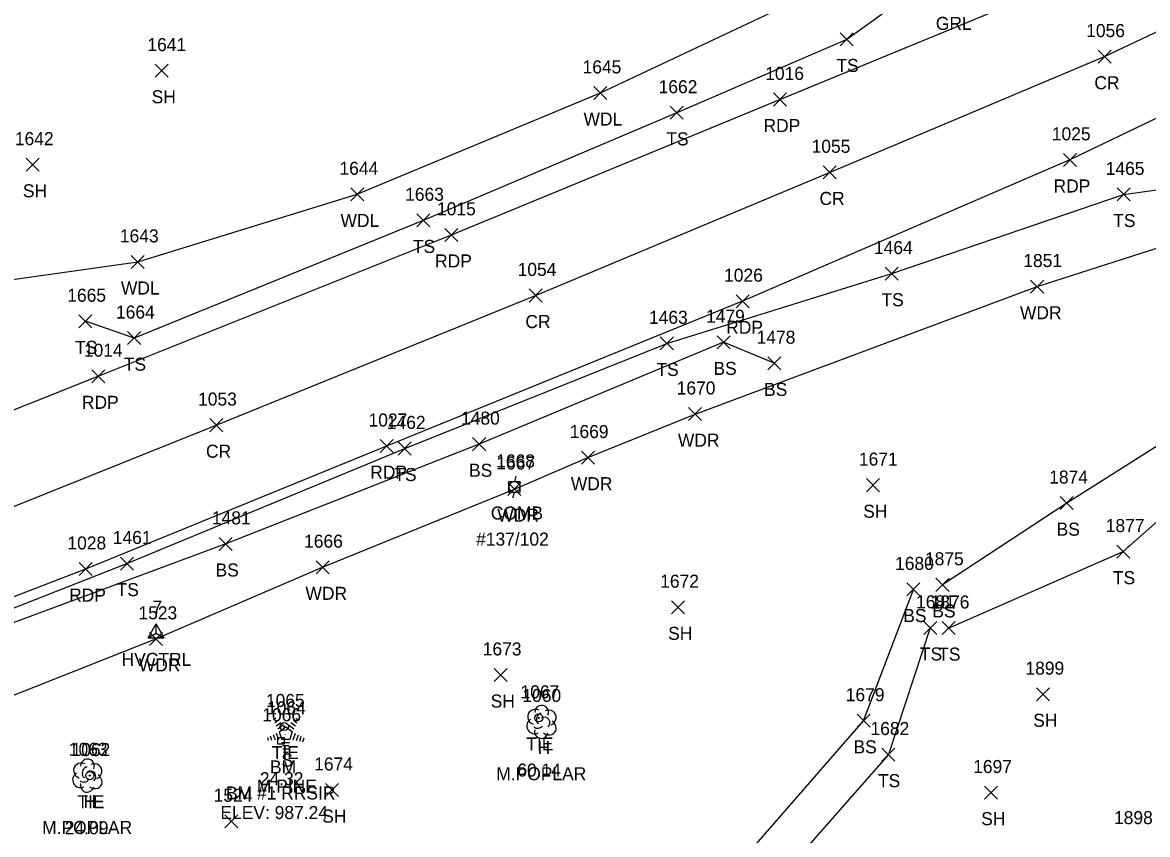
# Model space of a CAD drawing. Extents: x 1633660 to 1636532, y 388643 to 392631.
# Drawn here: x 1634224 to 1634396.6, y 388797.6 to 388922.1 of the extents above; entities that cross this region are included whole.
import ezdxf

# ---------------------------------------------------------------- set-up
doc = ezdxf.new("R2010")
doc.units = 0
for name, color, linetype in [('C_A', 7, 'Continuous'), ('C_C', 7, 'Continuous'), ('C_I', 7, 'Continuous'), ('CBP', 7, 'Continuous'), ('CPBM', 7, 'Continuous'), ('CPSM', 7, 'Continuous'), ('L_A', 7, 'Continuous'), ('L_C', 7, 'Continuous'), ('L_I', 7, 'Continuous'), ('L_TIC', 7, 'Continuous'), ('LAWA', 7, 'Continuous'), ('LELB', 7, 'Continuous'), ('LTC', 7, 'Continuous'), ('LTD', 7, 'Continuous'), ('P_A', 7, 'Continuous'), ('P_I', 7, 'Continuous'), ('P_TIC', 7, 'Continuous'), ('PET', 7, 'Continuous'), ('PRC', 7, 'Continuous'), ('R_A', 7, 'Continuous'), ('U_A', 7, 'Continuous'), ('U_C', 7, 'Continuous'), ('U_I', 7, 'Continuous'), ('UP', 7, 'Continuous')]:
    doc.layers.add(name, color=color, linetype=linetype)

msp = doc.modelspace()

# ---------------------------------------------------------------- linework, layer by layer
at = {"layer": 'CBP'}
for centre, radius in [((1634303.22, 388815.45), 0.625), ((1634264.16, 388814.12), 0.625), ((1634264.16, 388814.12), 0.0833), ((1634303.22, 388815.45), 0.0833), ((1634234.32, 388806.59), 0.625), ((1634234.32, 388806.59), 0.0833)]:
    msp.add_circle(centre, radius, dxfattribs=at)
at = {"layer": 'CPBM'}
for p, q in [((1634263.15, 388811.43), (1634263.15, 388812.43)), ((1634263.15, 388812.43), (1634264.15, 388812.43)), ((1634264.15, 388812.43), (1634264.15, 388811.43)), ((1634264.15, 388811.43), (1634263.15, 388811.43)), ((1634263.65, 388811.93), (1634263.65, 388811.93)), ((1634263.65, 388811.93), (1634263.65, 388811.93))]:
    msp.add_line(p, q, dxfattribs=at)
at = {"layer": 'CPSM'}
for p, q in [((1634243.25, 388827.71), (1634244.5, 388829.88)), ((1634245.75, 388827.71), (1634244.5, 388829.88)), ((1634244.5, 388828.43), (1634244.5, 388829.88)), ((1634243.25, 388827.71), (1634244.5, 388828.43)), ((1634243.25, 388827.71), (1634245.75, 388827.71)), ((1634244.5, 388828.43), (1634244.5, 388828.43)), ((1634244.5, 388828.43), (1634245.75, 388827.71))]:
    msp.add_line(p, q, dxfattribs=at)
at = {"layer": 'L_TIC'}
for points in [[(1634349.49, 388918.54), (1634351.49, 388920.54)], [(1634351.49, 388918.54), (1634349.49, 388920.54)], [(1634244.33, 388913.74), (1634246.33, 388915.74)], [(1634246.33, 388913.74), (1634244.33, 388915.74)], [(1634311.68, 388910.32), (1634313.68, 388912.32)], [(1634313.68, 388910.32), (1634311.68, 388912.32)], [(1634323.4, 388907.28), (1634325.4, 388909.28)], [(1634325.4, 388907.28), (1634323.4, 388909.28)], [(1634224.55, 388899.31), (1634226.55, 388901.31)], [(1634226.55, 388899.31), (1634224.55, 388901.31)], [(1634274.37, 388894.77), (1634276.37, 388896.77)], [(1634276.37, 388894.77), (1634274.37, 388896.77)], [(1634391.97, 388894.75), (1634393.97, 388896.75)], [(1634393.97, 388894.75), (1634391.97, 388896.75)], [(1634284.5, 388890.78), (1634286.5, 388892.78)], [(1634286.5, 388890.78), (1634284.5, 388892.78)], [(1634240.67, 388884.4), (1634242.67, 388886.4)], [(1634242.67, 388884.4), (1634240.67, 388886.4)], [(1634356.4, 388882.6), (1634358.4, 388884.6)], [(1634358.4, 388882.6), (1634356.4, 388884.6)], [(1634378.71, 388880.61), (1634380.71, 388882.61)], [(1634380.71, 388880.61), (1634378.71, 388882.61)], [(1634232.64, 388875.29), (1634234.64, 388877.29)], [(1634234.64, 388875.29), (1634232.64, 388877.29)], [(1634240.12, 388872.71), (1634242.12, 388874.71)], [(1634242.12, 388872.71), (1634240.12, 388874.71)], [(1634321.87, 388871.9), (1634323.87, 388873.9)], [(1634323.87, 388871.9), (1634321.87, 388873.9)], [(1634330.59, 388872.07), (1634332.59, 388874.07)], [(1634332.59, 388872.07), (1634330.59, 388874.07)], [(1634338.35, 388868.85), (1634340.35, 388870.85)], [(1634340.35, 388868.85), (1634338.35, 388870.85)], [(1634326.21, 388861.06), (1634328.21, 388863.06)], [(1634328.21, 388861.06), (1634326.21, 388863.06)], [(1634281.64, 388855.78), (1634283.64, 388857.78)], [(1634283.64, 388855.78), (1634281.64, 388857.78)], [(1634293.07, 388856.44), (1634295.07, 388858.44)], [(1634295.07, 388856.44), (1634293.07, 388858.44)], [(1634309.77, 388854.38), (1634311.77, 388856.38)], [(1634311.77, 388854.38), (1634309.77, 388856.38)], [(1634353.52, 388850.15), (1634355.52, 388852.15)], [(1634355.52, 388850.15), (1634353.52, 388852.15)], [(1634298.49, 388849.56), (1634300.49, 388851.56)], [(1634300.49, 388849.56), (1634298.49, 388851.56)], [(1634383.25, 388847.4), (1634385.25, 388849.4)], [(1634385.25, 388847.4), (1634383.25, 388849.4)], [(1634254.17, 388841.14), (1634256.17, 388843.14)], [(1634256.17, 388841.14), (1634254.17, 388843.14)], [(1634391.92, 388839.96), (1634393.92, 388841.96)], [(1634393.92, 388839.96), (1634391.92, 388841.96)], [(1634239.01, 388838.13), (1634241.01, 388840.13)], [(1634241.01, 388838.13), (1634239.01, 388840.13)], [(1634269.05, 388837.56), (1634271.05, 388839.56)], [(1634271.05, 388837.56), (1634269.05, 388839.56)], [(1634364.18, 388834.86), (1634366.18, 388836.86)], [(1634366.18, 388834.86), (1634364.18, 388836.86)], [(1634359.72, 388834.15), (1634361.72, 388836.15)], [(1634361.72, 388834.15), (1634359.72, 388836.15)], [(1634323.59, 388831.42), (1634325.59, 388833.42)], [(1634325.59, 388831.42), (1634323.59, 388833.42)], [(1634362.3, 388828.26), (1634364.3, 388830.26)], [(1634364.3, 388828.26), (1634362.3, 388830.26)], [(1634365.11, 388828.23), (1634367.11, 388830.23)], [(1634367.11, 388828.23), (1634365.11, 388830.23)], [(1634243.47, 388826.57), (1634245.47, 388828.57)], [(1634245.47, 388826.57), (1634243.47, 388828.57)], [(1634296.36, 388821.03), (1634298.36, 388823.03)], [(1634298.36, 388821.03), (1634296.36, 388823.03)], [(1634379.61, 388818.08), (1634381.61, 388820.08)], [(1634381.61, 388818.08), (1634379.61, 388820.08)], [(1634352.08, 388814.01), (1634354.08, 388816.01)], [(1634354.08, 388814.01), (1634352.08, 388816.01)], [(1634355.87, 388808.82), (1634357.87, 388810.82)], [(1634357.87, 388808.82), (1634355.87, 388810.82)], [(1634270.49, 388803.38), (1634272.49, 388805.38)], [(1634272.49, 388803.38), (1634270.49, 388805.38)], [(1634371.63, 388802.99), (1634373.63, 388804.99)], [(1634373.63, 388802.99), (1634371.63, 388804.99)], [(1634255.02, 388798.58), (1634257.02, 388800.58)], [(1634257.02, 388798.58), (1634255.02, 388800.58)]]:
    msp.add_lwpolyline(points, dxfattribs=at)
at = {"layer": 'LAWA'}
for points in [[(1634029.51, 388906.75), (1634042.75, 388866.2), (1634043.29, 388851.86), (1634059.73, 388819.64), (1634086.07, 388831.91), (1634132.5, 388845.49), (1634141.64, 388844.49), (1634171.78, 388858.91), (1634210.32, 388873.4), (1634220.65, 388882.43), (1634241.67, 388885.4), (1634275.37, 388895.77), (1634312.68, 388911.32), (1634346.59, 388927.34), (1634362.7, 388937.8), (1634391.49, 388949.24), (1634419.55, 388956.24), (1634431.93, 388958.02)], [(1634130.81, 388762.97), (1634125.77, 388773.71), (1634128.73, 388780.91), (1634147.8, 388788.83), (1634164.31, 388795.2), (1634191.33, 388807.23), (1634212.88, 388815.09), (1634244.47, 388827.57), (1634270.05, 388838.56), (1634299.49, 388850.56), (1634310.77, 388855.38), (1634327.21, 388862.06), (1634379.71, 388881.61), (1634402.37, 388888.88), (1634424.47, 388897.46), (1634452.16, 388917.36), (1634475.03, 388932.29), (1634483.74, 388944.66)]]:
    msp.add_lwpolyline(points, dxfattribs=at)
at = {"layer": 'LELB'}
for points in [[(1634445.58, 388960.23), (1634426.88, 388952.08), (1634393.48, 388937.2), (1634364.77, 388929.81), (1634350.49, 388919.54), (1634324.4, 388908.28), (1634285.5, 388891.78), (1634241.12, 388873.71), (1634233.64, 388876.29)], [(1634125.58, 388742.69), (1634122.38, 388746.52), (1634122.38, 388759.17), (1634119.85, 388773.41), (1634127.61, 388794.7), (1634159.93, 388808.1), (1634199.65, 388823.28), (1634240.01, 388839.13), (1634282.64, 388856.78), (1634322.87, 388872.9), (1634357.4, 388883.6), (1634392.97, 388895.75), (1634413.99, 388898.72), (1634440.42, 388919.1), (1634461.6, 388936.25), (1634480.46, 388947.83), (1634480.68, 388954.28)], [(1634584.89, 388915.4), (1634565.24, 388902.91), (1634528.64, 388898.73), (1634496.98, 388906.62), (1634477.85, 388894.65), (1634446.93, 388893.09), (1634415.16, 388876.74), (1634407.22, 388862.91), (1634384.25, 388848.4), (1634365.18, 388835.86)], [(1634366.11, 388829.23), (1634392.92, 388840.96), (1634414.75, 388860.24), (1634439.48, 388873.42), (1634473.36, 388870.48), (1634511.37, 388872.55), (1634556.17, 388880.75), (1634584.64, 388898.02), (1634601.64, 388909.04)], [(1634339.35, 388869.85), (1634331.59, 388873.07), (1634294.07, 388857.44), (1634255.17, 388842.14), (1634212.56, 388826.33), (1634166.48, 388807.72), (1634131.43, 388792.51), (1634129.2, 388785.04)], [(1634262.35, 388776.83), (1634280.42, 388782.29), (1634296.72, 388784.56), (1634333.52, 388792.53), (1634353.08, 388815.01), (1634360.72, 388835.15)], [(1634363.3, 388829.26), (1634356.87, 388809.82), (1634337.14, 388787.4), (1634300.22, 388782.34), (1634284.7, 388776.15), (1634269.21, 388771.48)]]:
    msp.add_lwpolyline(points, dxfattribs=at)
at = {"layer": 'LTC'}
for p, q in [((1634262.52, 388815.18), (1634262.88, 388815.44)), ((1634262.73, 388814.72), (1634263.26, 388815.1)), ((1634262.94, 388814.25), (1634263.65, 388814.76)), ((1634263.15, 388813.79), (1634264.03, 388814.42)), ((1634263.38, 388813.33), (1634264.39, 388814.07)), ((1634264.39, 388814.07), (1634265.39, 388813.34)), ((1634264.81, 388814.38), (1634265.62, 388813.79)), ((1634265.18, 388814.73), (1634265.86, 388814.23)), ((1634265.55, 388815.08), (1634266.1, 388814.68)), ((1634265.92, 388815.42), (1634266.34, 388815.12)), ((1634261.56, 388812.46), (1634261.71, 388811.99)), ((1634262.01, 388812.68), (1634262.22, 388812.03)), ((1634262.47, 388812.9), (1634262.74, 388812.06)), ((1634262.92, 388813.11), (1634263.25, 388812.09)), ((1634263.38, 388813.33), (1634263.76, 388812.14)), ((1634265, 388812.14), (1634263.76, 388812.14)), ((1634265.39, 388813.34), (1634265, 388812.14)), ((1634265.82, 388813.07), (1634265.49, 388812.03)), ((1634266.27, 388812.82), (1634265.98, 388811.94)), ((1634266.71, 388812.57), (1634266.48, 388811.84)), ((1634267.16, 388812.32), (1634266.97, 388811.75)), ((1634264.96, 388811.64), (1634263.81, 388811.64)), ((1634264.87, 388811.14), (1634263.88, 388811.14)), ((1634264.79, 388810.64), (1634263.96, 388810.64)), ((1634264.71, 388810.14), (1634264.03, 388810.14))]:
    msp.add_line(p, q, dxfattribs=at)
at = {"layer": 'LTD'}
for p, q in [((1634303.61, 388814.89), (1634303.61, 388814.89)), ((1634303.61, 388814.89), (1634303.61, 388814.89)), ((1634233.91, 388806.64), (1634233.91, 388806.64)), ((1634233.91, 388806.64), (1634233.91, 388806.64))]:
    msp.add_line(p, q, dxfattribs=at)
for centre in [(1634303.66, 388816.32), (1634233.96, 388808.08)]:
    msp.add_arc(centre, 1.05, 335.5272, 180.9563, dxfattribs=at)
for centre, major_axis, ratio, start_param, end_param in [((1634302.82, 388815.55), (1.21, -0.51), 0.895232, 1.570796, 4.712389), ((1634303.4, 388815.35), (-0.208, -0.792), 0.645439, 3.141593, 6.283185), ((1634304.11, 388814.72), (-0.5, 0.667), 0.989748, 3.141593, 6.283185), ((1634304.65, 388815.47), (-1.14, -0.48), 0.949671, 1.570796, 4.712389), ((1634302.53, 388814.18), (0.58, -1.04), 0.959034, 3.141593, 6.283185), ((1634303.15, 388814.14), (-0.625, -0.083), 0.423636, 0, 3.141593), ((1634304.61, 388814.05), (-1.09, 0.79), 0.841452, 1.570796, 4.712389), ((1634303.61, 388813.39), (0.26, 1.06), 0.942809, 1.570796, 4.712389), ((1634233.12, 388807.31), (1.21, -0.51), 0.895232, 1.570796, 4.712389), ((1634232.83, 388805.93), (0.58, -1.04), 0.959034, 3.141593, 6.283185), ((1634233.7, 388807.1), (-0.208, -0.792), 0.645439, 3.141593, 6.283185), ((1634234.41, 388806.47), (-0.5, 0.667), 0.989748, 3.141593, 6.283185), ((1634234.95, 388807.22), (-1.14, -0.48), 0.949671, 1.570796, 4.712389), ((1634233.91, 388805.14), (0.26, 1.06), 0.942809, 1.570796, 4.712389), ((1634233.45, 388805.89), (-0.625, -0.083), 0.423636, 0, 3.141593), ((1634234.91, 388805.81), (-1.09, 0.79), 0.841452, 1.570796, 4.712389)]:
    msp.add_ellipse(centre, major_axis=major_axis, ratio=ratio, start_param=start_param, end_param=end_param, dxfattribs=at)
at = {"layer": 'P_TIC'}
for points in [[(1634389.05, 388915.89), (1634391.05, 388917.89)], [(1634391.05, 388915.89), (1634389.05, 388917.89)], [(1634339.23, 388909.32), (1634341.23, 388911.32)], [(1634341.23, 388909.32), (1634339.23, 388911.32)], [(1634383.73, 388900.05), (1634385.73, 388902.05)], [(1634385.73, 388900.05), (1634383.73, 388902.05)], [(1634346.86, 388898.14), (1634348.86, 388900.14)], [(1634348.86, 388898.14), (1634346.86, 388900.14)], [(1634288.81, 388888.55), (1634290.81, 388890.55)], [(1634290.81, 388888.55), (1634288.81, 388890.55)], [(1634301.74, 388879.25), (1634303.74, 388881.25)], [(1634303.74, 388879.25), (1634301.74, 388881.25)], [(1634333.49, 388878.37), (1634335.49, 388880.37)], [(1634335.49, 388878.37), (1634333.49, 388880.37)], [(1634234.61, 388866.86), (1634236.61, 388868.86)], [(1634236.61, 388866.86), (1634234.61, 388868.86)], [(1634252.71, 388859.36), (1634254.71, 388861.36)], [(1634254.71, 388859.36), (1634252.71, 388861.36)], [(1634278.87, 388856.15), (1634280.87, 388858.15)], [(1634280.87, 388856.15), (1634278.87, 388858.15)], [(1634232.66, 388837.29), (1634234.66, 388839.29)], [(1634234.66, 388837.29), (1634232.66, 388839.29)]]:
    msp.add_lwpolyline(points, dxfattribs=at)
at = {"layer": 'PET'}
msp.add_lwpolyline([(1634182.59, 388846.73), (1634235.61, 388867.86), (1634289.81, 388889.55), (1634340.23, 388910.32), (1634383.94, 388928.36), (1634416.96, 388942.42), (1634441.99, 388954.99), (1634450.02, 388959.85), (1634465.24, 388958.09), (1634480.35, 388956.01), (1634458.41, 388940.87), (1634427.91, 388921.75), (1634384.73, 388901.05), (1634334.49, 388879.37), (1634279.87, 388857.15), (1634233.66, 388838.29), (1634176.14, 388816.11)], dxfattribs=at)
at = {"layer": 'PRC'}
msp.add_lwpolyline([(1633685.21, 388740.89), (1633722.47, 388753.09), (1633765.95, 388761.74), (1633808.84, 388766.45), (1633860.63, 388768.05), (1633911.93, 388769.08), (1633965.45, 388772.58), (1634019.68, 388781.06), (1634071.37, 388793.87), (1634111.14, 388806.36), (1634160.92, 388824.06), (1634207.93, 388842.02), (1634253.71, 388860.36), (1634302.74, 388880.25), (1634347.86, 388899.14), (1634390.05, 388916.89), (1634425.6, 388933.8), (1634443.27, 388943.77), (1634464.46, 388957.57)], dxfattribs=at)
at = {"layer": 'UP'}
for p, q in [((1634299.72, 388852.54), (1634299.47, 388851.71)), ((1634298.64, 388850.04), (1634298.64, 388851.71)), ((1634298.64, 388851.71), (1634300.31, 388851.71)), ((1634299.47, 388850.88), (1634299.47, 388850.88)), ((1634300.31, 388851.71), (1634300.31, 388850.04)), ((1634300.31, 388850.04), (1634298.64, 388850.04)), ((1634299.22, 388849.21), (1634299.47, 388850.04))]:
    msp.add_line(p, q, dxfattribs=at)
msp.add_circle((1634299.47, 388850.88), 0.833, dxfattribs=at)

# ---------------------------------------------------------------- texts
at = {"layer": 'C_A'}
for s, p in [('HVCTRL', (1634239.19, 388823.43)), ('TIE', (1634301.3, 388810.45)), ('TIE', (1634262.24, 388809.12)), ('BM', (1634261.97, 388806.93)), ('TIE', (1634232.4, 388801.59))]:
    msp.add_text(s, height=2, dxfattribs=at).set_placement(p)
at = {"layer": 'C_C'}
for s, p in [('24.32', (1634260.41, 388805.12)), ('60.14', (1634299.92, 388806.45)), ('BM #1 RRSIR', (1634255.22, 388802.93)), ('ELEV: 987.24', (1634254.36, 388799.93)), ('24.09', (1634230.48, 388797.59))]:
    msp.add_text(s, height=2, dxfattribs=at).set_placement(p)
at = {"layer": 'C_I'}
for s, p in [('7', (1634243.93, 388831.43)), ('1065', (1634261.34, 388817.12)), ('1067', (1634300.41, 388818.45)), ('1066', (1634260.78, 388814.93)), ('1062', (1634231.5, 388809.59))]:
    msp.add_text(s, height=2, dxfattribs=at).set_placement(p)
at = {"layer": 'L_A'}
for s, p in [('TS', (1634348.9, 388914.54)), ('SH', (1634243.81, 388909.74)), ('WDL', (1634310.09, 388906.32)), ('TS', (1634322.8, 388903.28)), ('SH', (1634224.04, 388895.31)), ('WDL', (1634272.79, 388890.77)), ('TS', (1634391.38, 388890.75)), ('TS', (1634283.91, 388886.78)), ('WDL', (1634239.09, 388880.4)), ('TS', (1634355.81, 388878.6)), ('WDR', (1634377.07, 388876.61)), ('TS', (1634232.05, 388871.29)), ('TS', (1634239.53, 388868.71)), ('TS', (1634321.28, 388867.9)), ('BS', (1634330.03, 388868.07)), ('BS', (1634337.79, 388864.85)), ('WDR', (1634324.57, 388857.06)), ('TS', (1634281.05, 388851.78)), ('BS', (1634292.52, 388852.44)), ('WDR', (1634308.14, 388850.38)), ('WDR', (1634296.85, 388845.56)), ('SH', (1634353.01, 388846.15)), ('BS', (1634382.69, 388843.4)), ('BS', (1634253.61, 388837.14)), ('TS', (1634391.33, 388835.96)), ('TS', (1634238.42, 388834.13)), ('WDR', (1634267.41, 388833.56)), ('BS', (1634363.62, 388830.86)), ('BS', (1634359.16, 388830.15)), ('SH', (1634323.07, 388827.42)), ('TS', (1634361.71, 388824.26)), ('TS', (1634364.52, 388824.23)), ('WDR', (1634241.83, 388822.57)), ('SH', (1634295.84, 388817.03)), ('SH', (1634379.1, 388814.08)), ('H', (1634303.04, 388809.89)), ('BS', (1634351.52, 388810.01)), ('S', (1634263.71, 388807.98)), ('TS', (1634355.28, 388804.82)), ('H', (1634233.35, 388801.64)), ('SH', (1634269.98, 388799.38)), ('SH', (1634371.12, 388798.99))]:
    msp.add_text(s, height=2, dxfattribs=at).set_placement(p)
at = {"layer": 'L_C'}
for s, p in [('M.POPLAR', (1634296.69, 388805.89)), ('M.PINE', (1634259.94, 388803.98)), ('M.POPLAR', (1634226.99, 388797.64))]:
    msp.add_text(s, height=2, dxfattribs=at).set_placement(p)
at = {"layer": 'L_I'}
for s, p in [('1641', (1634243.15, 388917.74)), ('1645', (1634309.94, 388914.32)), ('1662', (1634321.61, 388911.28)), ('1642', (1634222.81, 388903.31)), ('1644', (1634272.63, 388898.77)), ('1465', (1634390.23, 388898.75)), ('1663', (1634282.71, 388894.78)), ('1643', (1634238.93, 388888.4)), ('1464', (1634354.66, 388886.6)), ('1851', (1634377.58, 388884.61)), ('1665', (1634230.85, 388879.29)), ('1664', (1634238.33, 388876.71)), ('1463', (1634320.13, 388875.9)), ('1479', (1634328.89, 388876.07)), ('1478', (1634336.65, 388872.85)), ('1670', (1634324.38, 388865.06)), ('1480', (1634291.29, 388860.44)), ('1462', (1634279.9, 388859.78)), ('1669', (1634307.98, 388858.38)), ('1667', (1634296.7, 388853.56)), ('1671', (1634352.35, 388854.15)), ('1874', (1634381.56, 388851.4)), ('1481', (1634253.05, 388845.14)), ('1877', (1634390.23, 388843.96)), ('1461', (1634237.84, 388842.13)), ('1666', (1634267.2, 388841.56)), ('1680', (1634357.9, 388838.15)), ('1875', (1634362.49, 388838.86)), ('1672', (1634321.85, 388835.42)), ('1681', (1634361.12, 388832.26)), ('1876', (1634363.36, 388832.23)), ('1523', (1634241.78, 388830.57)), ('1673', (1634294.62, 388825.03)), ('1899', (1634377.91, 388822.08)), ('1060', (1634300.7, 388817.89)), ('1679', (1634350.33, 388818.01)), ('1064', (1634261.51, 388815.98)), ('1682', (1634354.13, 388812.82)), ('1063', (1634231.09, 388809.64)), ('1674', (1634268.75, 388807.38)), ('1697', (1634369.89, 388806.99)), ('1524', (1634253.32, 388802.58)), ('1898', (1634391.5, 388799.15))]:
    msp.add_text(s, height=2, dxfattribs=at).set_placement(p)
at = {"layer": 'LTC'}
msp.add_text('.', height=1.04, rotation=270, dxfattribs=at).set_placement((1634264.27, 388813.08))
at = {"layer": 'P_A'}
for s, p in [('CR', (1634388.49, 388911.89)), ('RDP', (1634337.71, 388905.32)), ('RDP', (1634382.22, 388896.05)), ('CR', (1634346.3, 388894.14)), ('RDP', (1634287.3, 388884.55)), ('CR', (1634301.17, 388875.25)), ('RDP', (1634331.98, 388874.37)), ('RDP', (1634233.1, 388862.86)), ('CR', (1634252.14, 388855.36)), ('RDP', (1634277.35, 388852.15)), ('RDP', (1634231.14, 388833.29))]:
    msp.add_text(s, height=2, dxfattribs=at).set_placement(p)
at = {"layer": 'P_I'}
for s, p in [('1056', (1634387.23, 388919.89)), ('1016', (1634337.97, 388913.32)), ('1025', (1634381.96, 388904.05)), ('1055', (1634345.09, 388902.14)), ('1015', (1634287.6, 388892.55)), ('1054', (1634299.97, 388883.25)), ('1026', (1634331.66, 388882.37)), ('1014', (1634233.4, 388870.86)), ('1053', (1634250.93, 388863.36)), ('1027', (1634277.09, 388860.15)), ('1028', (1634230.88, 388841.29))]:
    msp.add_text(s, height=2, dxfattribs=at).set_placement(p)
at = {"layer": 'R_A'}
msp.add_text('GRL', height=2, dxfattribs=at).set_placement((1634364.16, 388920.99))
at = {"layer": 'U_A'}
msp.add_text('COMB', height=2, dxfattribs=at).set_placement((1634295.86, 388845.88))
at = {"layer": 'U_C'}
msp.add_text('#137/102', height=2, dxfattribs=at).set_placement((1634293.6, 388841.88))
at = {"layer": 'U_I'}
msp.add_text('1668', height=2, dxfattribs=at).set_placement((1634296.68, 388853.88))

doc.saveas('drawing.dxf')
